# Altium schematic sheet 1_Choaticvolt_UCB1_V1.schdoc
size 309 x 223 mm; Symbol: Sheet-Symbol_A4; Device: Sheet-Symbol_A4; @Project Name: Chaoticvolt-SensorHUB-v1.0; @Page Count: 1; @Update Date: 2024-12-07; @Create Date: 2024-12-07; @Schematic Name: Choaticvolt_UCB1_V1; @Page No: 1; @Page Name: Choaticvolt_UCB1_V1; Company: EasyEDA.com; Reviewed: EasyEDA; Version: V0.1; Page Size: A4; Part Number: JLCPCB-002; Drawn: EasyEDA; Title Block Position: 3; Width: 1170; Height: 825; Region Start: 1; X Region Count: 6; Y Region Count: 4; Blade Width: 10; @Board Name: Choaticvolt_UCB1_V1; @Create Time: 10:24:35; @Update Time: 13:48:08
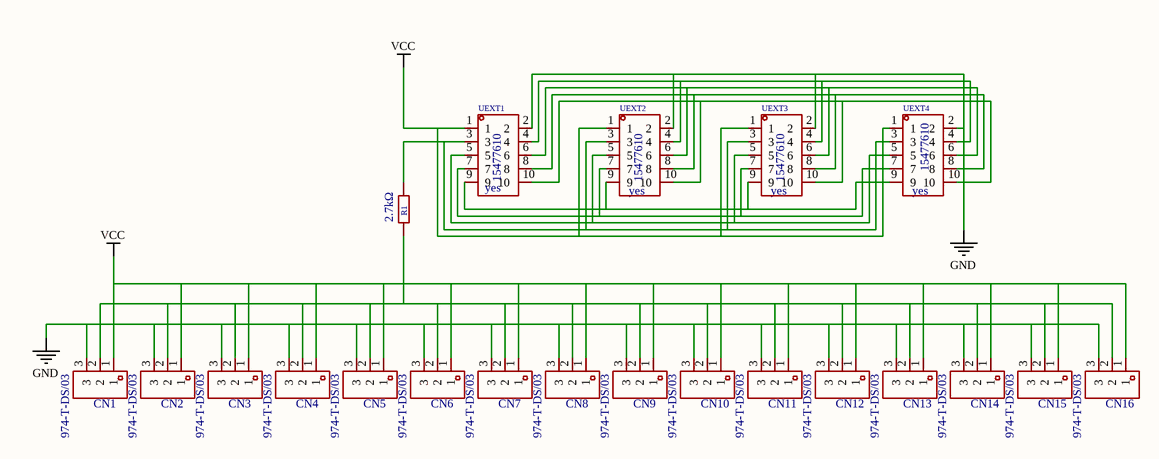
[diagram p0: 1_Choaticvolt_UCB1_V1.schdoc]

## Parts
CN1  974-T-DS/03  [CONN-TH_3P-P5.00_WECO_974-T-DS-03]  (value not drawn)
CN2  974-T-DS/03  [CONN-TH_3P-P5.00_WECO_974-T-DS-03]  (value not drawn)
CN3  974-T-DS/03  [CONN-TH_3P-P5.00_WECO_974-T-DS-03]  (value not drawn)
CN4  974-T-DS/03  [CONN-TH_3P-P5.00_WECO_974-T-DS-03]  (value not drawn)
CN5  974-T-DS/03  [CONN-TH_3P-P5.00_WECO_974-T-DS-03]  (value not drawn)
CN6  974-T-DS/03  [CONN-TH_3P-P5.00_WECO_974-T-DS-03]  (value not drawn)
CN7  974-T-DS/03  [CONN-TH_3P-P5.00_WECO_974-T-DS-03]  (value not drawn)
CN8  974-T-DS/03  [CONN-TH_3P-P5.00_WECO_974-T-DS-03]  (value not drawn)
CN9  974-T-DS/03  [CONN-TH_3P-P5.00_WECO_974-T-DS-03]  (value not drawn)
CN10  974-T-DS/03  [CONN-TH_3P-P5.00_WECO_974-T-DS-03]  (value not drawn)
CN11  974-T-DS/03  [CONN-TH_3P-P5.00_WECO_974-T-DS-03]  (value not drawn)
CN12  974-T-DS/03  [CONN-TH_3P-P5.00_WECO_974-T-DS-03]  (value not drawn)
CN13  974-T-DS/03  [CONN-TH_3P-P5.00_WECO_974-T-DS-03]  (value not drawn)
CN14  974-T-DS/03  [CONN-TH_3P-P5.00_WECO_974-T-DS-03]  (value not drawn)
CN15  974-T-DS/03  [CONN-TH_3P-P5.00_WECO_974-T-DS-03]  (value not drawn)
CN16  974-T-DS/03  [CONN-TH_3P-P5.00_WECO_974-T-DS-03]  (value not drawn)
R1  2.7kΩ  [RES-TH_BD3.3-L9.0-P13.00-D0.6]  (value not drawn)
UEXT1  Add into BOM: yes  [IDC-TH_15477610]  (hidden comment: 15477610)
UEXT2  Add into BOM: yes  [IDC-TH_15477610]  (hidden comment: 15477610)
UEXT3  Add into BOM: yes  [IDC-TH_15477610]  (hidden comment: 15477610)
UEXT4  Add into BOM: yes  [IDC-TH_15477610]  (hidden comment: 15477610)

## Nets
GND: CN1.3 CN2.3 CN3.3 CN4.3 CN5.3 CN6.3 CN7.3 CN8.3 CN9.3 CN10.3 CN11.3 CN12.3 CN13.3 CN14.3 CN15.3 CN16.3 UEXT1.2 UEXT2.2 UEXT3.2 UEXT4.2
VCC: CN1.1 CN2.1 CN3.1 CN4.1 CN5.1 CN6.1 CN7.1 CN8.1 CN9.1 CN10.1 CN11.1 CN12.1 CN13.1 CN14.1 CN15.1 CN16.1 UEXT1.1 UEXT2.1 UEXT3.1 UEXT4.1
NetCN1_2: CN1.2 CN2.2 CN3.2 CN4.2 CN5.2 CN6.2 CN7.2 CN8.2 CN9.2 CN10.2 CN11.2 CN12.2 CN13.2 CN14.2 CN15.2 CN16.2 R1.1
NetR1_2: R1.2 UEXT1.3 UEXT2.3 UEXT3.3 UEXT4.3
NetUEXT1_4: UEXT1.4 UEXT2.4 UEXT3.4 UEXT4.4
NetUEXT1_5: UEXT1.5 UEXT2.5 UEXT3.5 UEXT4.5
NetUEXT1_6: UEXT1.6 UEXT2.6 UEXT3.6 UEXT4.6
NetUEXT1_7: UEXT1.7 UEXT2.7 UEXT3.7 UEXT4.7
NetUEXT1_8: UEXT1.8 UEXT2.8 UEXT3.8 UEXT4.8
NetUEXT1_9: UEXT1.9 UEXT2.9 UEXT3.9 UEXT4.9
NetUEXT1_10: UEXT1.10 UEXT2.10 UEXT3.10 UEXT4.10

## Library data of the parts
CN1-CN16 = 974-T-DS/03: Structure:1x3P Pitch:5mm Color:Gray Mounting Style:Bend insert Number of Pins:3P Number of Rows:1 Number of PINs Per Row:3 Screw Specification:M3 Current Rating (Max):24A Voltage Rating (Max):250V Wire Gauge - AWG:12~18；12~16 Wire Gauge - AWG:12~18；12~16; Manufacturer: WECO(威克德诺); Add into BOM: yes; Structure: 1x3P; Pitch: 5mm; Number of PINs Per Row: 3; Screw Specification: M3; Current Rating (Max): 24A; Voltage Rating (Max): 250V; Wire Gauge - mm2: 0.75~4；1~6
R1 = MFR1WSJT-52-2K7: Type:Metal Film Resistors Resistance: Tolerance:±5% Tolerance:±5% Power(Watts):1W Operating Temperature Range:-55℃~+155℃ Operating Temperature Range:-55℃~+155℃; Manufacturer: YAGEO(国巨); Add into BOM: yes; Tolerance: ±5%; Power(Watts): 1W
UEXT1-UEXT4 = 15477610: Pins Structure:2x5P Pitch:2.54mm Mounting Style:- Reference Series:- Number of Pins:10P Number of Rows:2 Number of PINs Per Row:5 Row Spacing:2.54mm Contact Material:Copper Alloy; Manufacturer: MOLEX; Pins Structure: 2x5P; Pitch: 2.54mm; Number of PINs Per Row: 5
